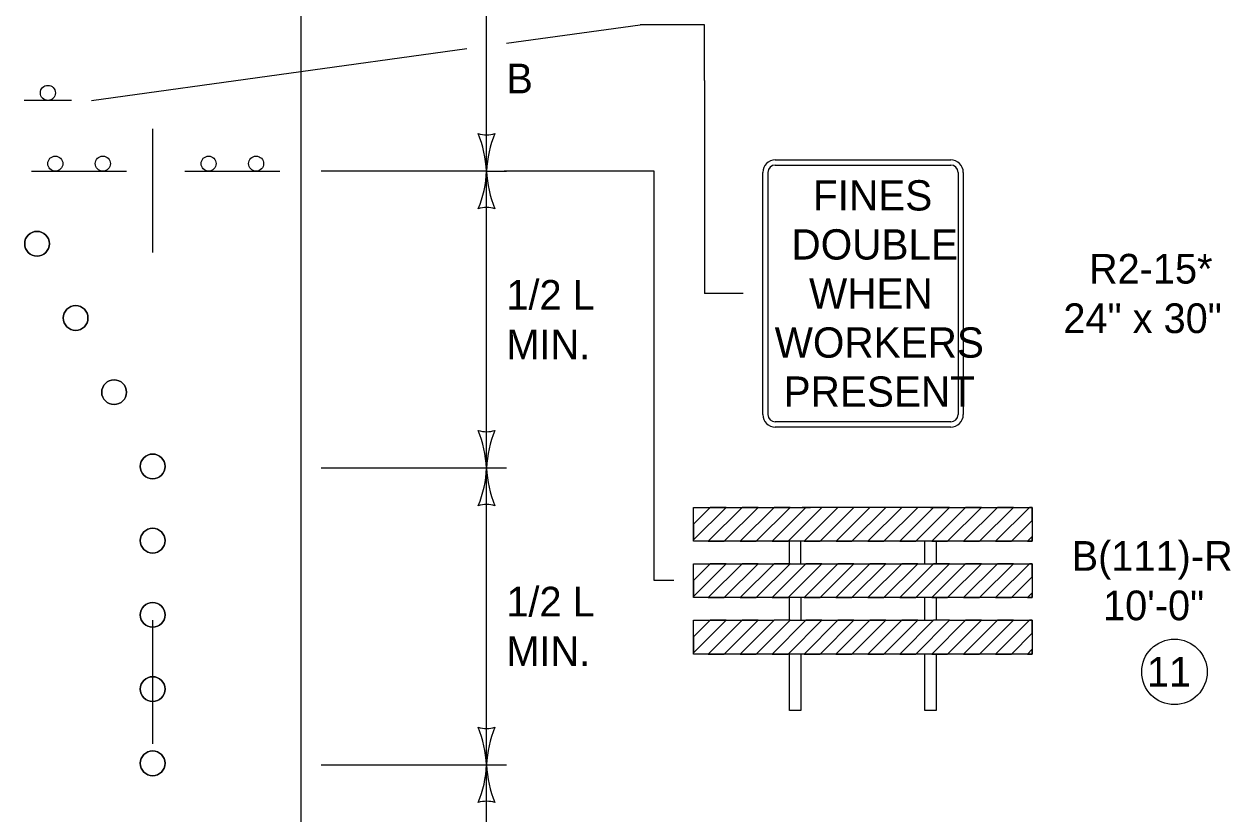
# Model space of a CAD drawing. Extents: x 49991.4 to 50021, y 49987.6 to 50011.4.
# Drawn here: x 50001.907 to 50004.345, y 49990.799 to 49992.395 of the extents above; entities that cross this region are included whole.
import ezdxf

# ---------------------------------------------------------------- set-up
doc = ezdxf.new("R2010")
doc.units = 0
for name, color, linetype in [('Level 1', 7, 'Continuous'), ('Level 2', 7, 'Continuous'), ('Level 3', 7, 'Continuous')]:
    doc.layers.add(name, color=color, linetype=linetype)

# ---------------------------------------------------------------- blocks, each defined once
blk = doc.blocks.new('ARR')
at = {"layer": 'Level 3'}
for centre, radius, start, end in [((1.53, 37.02), 37.05, 247.456, 267.6395), ((-21.37, 0), 9.13, 342.1388, 17.8612), ((1.92, -38.79), 38.83, 92.8273, 112.0772)]:
    blk.add_arc(centre, radius, start, end, dxfattribs=at)

msp = doc.modelspace()

# ---------------------------------------------------------------- linework, layer by layer
at = {"layer": 'Level 1'}
for p, q in [((50002.4673, 49988.1586), (50002.4673, 49992.9404)), ((50002.0033, 49992.2408), (50001.9073, 49992.2408)), ((50002.167, 49991.9331), (50002.167, 49992.1831)), ((50003.425, 49992.1205), (50003.7795, 49992.1205)), ((50003.425, 49992.11), (50003.7795, 49992.11)), ((50003.6023, 49992.1205), (50003.6023, 49992.1205)), ((50001.9223, 49992.0977), (50002.0183, 49992.0977)), ((50002.0183, 49992.0977), (50002.1143, 49992.0977)), ((50002.232, 49992.0977), (50002.328, 49992.0977)), ((50002.328, 49992.0977), (50002.424, 49992.0977)), ((50003.3997, 49991.6058), (50003.3997, 49992.0952)), ((50003.4103, 49991.6058), (50003.4103, 49992.0952)), ((50003.7942, 49992.0952), (50003.7942, 49991.6058)), ((50003.8048, 49992.0952), (50003.8048, 49991.6058)), ((50001.9084, 49991.951), (50001.9084, 49991.951)), ((50001.9863, 49991.801), (50001.9863, 49991.801)), ((50002.0641, 49991.651), (50002.0641, 49991.651)), ((50003.7795, 49991.591), (50003.425, 49991.591)), ((50003.7795, 49991.5805), (50003.425, 49991.5805)), ((50002.142, 49991.501), (50002.142, 49991.501)), ((50003.2599, 49991.3524), (50003.3258, 49991.4182)), ((50003.2599, 49991.3846), (50003.2935, 49991.4182)), ((50003.2935, 49991.4182), (50003.2599, 49991.3846)), ((50003.2599, 49991.3524), (50003.3258, 49991.4182)), ((50003.2896, 49991.3498), (50003.358, 49991.4182)), ((50003.358, 49991.4182), (50003.2896, 49991.3498)), ((50003.3218, 49991.3498), (50003.3902, 49991.4182)), ((50003.3218, 49991.3498), (50003.3902, 49991.4182)), ((50003.3541, 49991.3498), (50003.4225, 49991.4182)), ((50003.4225, 49991.4182), (50003.3541, 49991.3498)), ((50003.3863, 49991.3498), (50003.4547, 49991.4182)), ((50003.3863, 49991.3498), (50003.4547, 49991.4182)), ((50003.4186, 49991.3498), (50003.4869, 49991.4182)), ((50003.4508, 49991.3498), (50003.5192, 49991.4182)), ((50003.4651, 49991.4182), (50003.4964, 49991.4182)), ((50003.7244, 49991.4182), (50003.4794, 49991.4182)), ((50003.4832, 49991.3498), (50003.5516, 49991.4182)), ((50003.5154, 49991.3498), (50003.5838, 49991.4182)), ((50003.5476, 49991.3498), (50003.616, 49991.4182)), ((50003.5798, 49991.3498), (50003.6482, 49991.4182)), ((50003.612, 49991.3498), (50003.6804, 49991.4182)), ((50003.6443, 49991.3498), (50003.7126, 49991.4182)), ((50003.6765, 49991.3498), (50003.7448, 49991.4182)), ((50003.7448, 49991.4182), (50003.7049, 49991.4182)), ((50003.7087, 49991.3498), (50003.7771, 49991.4182)), ((50003.7409, 49991.3498), (50003.8093, 49991.4182)), ((50003.8093, 49991.4182), (50003.7409, 49991.3498)), ((50003.7732, 49991.3498), (50003.8416, 49991.4182)), ((50003.7732, 49991.3498), (50003.8416, 49991.4182)), ((50003.8054, 49991.3498), (50003.8738, 49991.4182)), ((50003.8738, 49991.4182), (50003.8054, 49991.3498)), ((50003.8376, 49991.3498), (50003.906, 49991.4182)), ((50003.8376, 49991.3498), (50003.906, 49991.4182)), ((50003.8699, 49991.3498), (50003.9383, 49991.4182)), ((50003.9383, 49991.4182), (50003.8699, 49991.3498)), ((50003.9021, 49991.3498), (50003.9439, 49991.3916)), ((50003.9021, 49991.3498), (50003.9439, 49991.3916)), ((50002.142, 49991.351), (50002.142, 49991.351)), ((50003.4765, 49991.3043), (50003.4765, 49991.3498)), ((50003.7273, 49991.3043), (50003.7273, 49991.3498)), ((50003.9344, 49991.3498), (50003.9439, 49991.3593)), ((50003.9439, 49991.3593), (50003.9344, 49991.3498)), ((50003.2599, 49991.2384), (50003.3258, 49991.3043)), ((50003.2599, 49991.2706), (50003.2935, 49991.3043)), ((50003.2935, 49991.3043), (50003.2599, 49991.2706)), ((50003.2599, 49991.2384), (50003.3258, 49991.3043)), ((50003.2896, 49991.2359), (50003.358, 49991.3043)), ((50003.358, 49991.3043), (50003.2896, 49991.2359)), ((50003.3218, 49991.2359), (50003.3902, 49991.3043)), ((50003.3218, 49991.2359), (50003.3902, 49991.3043)), ((50003.3541, 49991.2359), (50003.4225, 49991.3043)), ((50003.4225, 49991.3043), (50003.3541, 49991.2359)), ((50003.3863, 49991.2359), (50003.4547, 49991.3043)), ((50003.3863, 49991.2359), (50003.4547, 49991.3043)), ((50003.4186, 49991.2359), (50003.4869, 49991.3043)), ((50003.4508, 49991.2359), (50003.5192, 49991.3043)), ((50003.483, 49991.2359), (50003.5514, 49991.3043)), ((50003.5153, 49991.2359), (50003.5837, 49991.3043)), ((50003.5475, 49991.2359), (50003.6159, 49991.3043)), ((50003.5797, 49991.2359), (50003.6481, 49991.3043)), ((50003.612, 49991.2359), (50003.6804, 49991.3043)), ((50003.6442, 49991.2359), (50003.7126, 49991.3043)), ((50003.6765, 49991.2359), (50003.7387, 49991.2981)), ((50003.7387, 49991.2659), (50003.7771, 49991.3043)), ((50003.7387, 49991.2981), (50003.7448, 49991.3043)), ((50003.7409, 49991.2359), (50003.8093, 49991.3043)), ((50003.8093, 49991.3043), (50003.7409, 49991.2359)), ((50003.7732, 49991.2359), (50003.8416, 49991.3043)), ((50003.7732, 49991.2359), (50003.8416, 49991.3043)), ((50003.8054, 49991.2359), (50003.8738, 49991.3043)), ((50003.8738, 49991.3043), (50003.8054, 49991.2359)), ((50003.8376, 49991.2359), (50003.906, 49991.3043)), ((50003.8376, 49991.2359), (50003.906, 49991.3043)), ((50003.8699, 49991.2359), (50003.9383, 49991.3043)), ((50003.9383, 49991.3043), (50003.8699, 49991.2359)), ((50003.9021, 49991.2359), (50003.9439, 49991.2776)), ((50003.9021, 49991.2359), (50003.9439, 49991.2776)), ((50003.7087, 49991.2359), (50003.7387, 49991.2659)), ((50003.9344, 49991.2359), (50003.9439, 49991.2454)), ((50003.9439, 49991.2454), (50003.9344, 49991.2359)), ((50002.142, 49991.201), (50002.142, 49991.201)), ((50002.1674, 49990.9404), (50002.1674, 49991.1904)), ((50003.2599, 49991.1244), (50003.3258, 49991.1903)), ((50003.2599, 49991.1567), (50003.2935, 49991.1903)), ((50003.2935, 49991.1903), (50003.2599, 49991.1567)), ((50003.2599, 49991.1244), (50003.3258, 49991.1903)), ((50003.2896, 49991.1219), (50003.358, 49991.1903)), ((50003.358, 49991.1903), (50003.2896, 49991.1219)), ((50003.3218, 49991.1219), (50003.3902, 49991.1903)), ((50003.3218, 49991.1219), (50003.3902, 49991.1903)), ((50003.3541, 49991.1219), (50003.4225, 49991.1903)), ((50003.4225, 49991.1903), (50003.3541, 49991.1219)), ((50003.3863, 49991.1219), (50003.4547, 49991.1903)), ((50003.3863, 49991.1219), (50003.4547, 49991.1903)), ((50003.4186, 49991.1219), (50003.4869, 49991.1903)), ((50003.4869, 49991.1903), (50003.4186, 49991.1219)), ((50003.4508, 49991.1219), (50003.5192, 49991.1903)), ((50003.4508, 49991.1219), (50003.5192, 49991.1903)), ((50003.483, 49991.1219), (50003.5514, 49991.1903)), ((50003.5514, 49991.1903), (50003.483, 49991.1219)), ((50003.5153, 49991.1219), (50003.5837, 49991.1903)), ((50003.5153, 49991.1219), (50003.5837, 49991.1903)), ((50003.5475, 49991.1219), (50003.6159, 49991.1903)), ((50003.6159, 49991.1903), (50003.5475, 49991.1219)), ((50003.5797, 49991.1219), (50003.6481, 49991.1903)), ((50003.5797, 49991.1219), (50003.6481, 49991.1903)), ((50003.612, 49991.1219), (50003.6804, 49991.1903)), ((50003.6804, 49991.1903), (50003.612, 49991.1219)), ((50003.6442, 49991.1219), (50003.7126, 49991.1903)), ((50003.6442, 49991.1219), (50003.7126, 49991.1903)), ((50003.6765, 49991.1219), (50003.7448, 49991.1903)), ((50003.7448, 49991.1903), (50003.6765, 49991.1219)), ((50003.7087, 49991.1219), (50003.7771, 49991.1903)), ((50003.7087, 49991.1219), (50003.7771, 49991.1903)), ((50003.7409, 49991.1219), (50003.8093, 49991.1903)), ((50003.8093, 49991.1903), (50003.7409, 49991.1219)), ((50003.7732, 49991.1219), (50003.8416, 49991.1903)), ((50003.7732, 49991.1219), (50003.8416, 49991.1903)), ((50003.8054, 49991.1219), (50003.8738, 49991.1903)), ((50003.8738, 49991.1903), (50003.8054, 49991.1219)), ((50003.8376, 49991.1219), (50003.906, 49991.1903)), ((50003.8376, 49991.1219), (50003.906, 49991.1903)), ((50003.8699, 49991.1219), (50003.9383, 49991.1903)), ((50003.9383, 49991.1903), (50003.8699, 49991.1219)), ((50003.9021, 49991.1219), (50003.9439, 49991.1637)), ((50003.9021, 49991.1219), (50003.9439, 49991.1637)), ((50003.9344, 49991.1219), (50003.9439, 49991.1315)), ((50003.9439, 49991.1315), (50003.9344, 49991.1219)), ((50002.142, 49991.051), (50002.142, 49991.051)), ((50002.142, 49990.901), (50002.142, 49990.901))]:
    msp.add_line(p, q, dxfattribs=at)
for points in [[(50003.7387, 49991.3498), (50003.2599, 49991.3498), (50003.2599, 49991.4182), (50003.4651, 49991.4182)], [(50003.3258, 49991.4182), (50003.2935, 49991.4182)], [(50003.3902, 49991.4182), (50003.358, 49991.4182)], [(50003.5192, 49991.4182), (50003.4964, 49991.4182), (50003.4869, 49991.4182), (50003.4186, 49991.3498), (50003.4508, 49991.3498), (50003.5192, 49991.4182)], [(50003.4547, 49991.4182), (50003.4225, 49991.4182)], [(50003.5838, 49991.4182), (50003.5516, 49991.4182), (50003.4832, 49991.3498), (50003.5154, 49991.3498), (50003.5838, 49991.4182)], [(50003.6482, 49991.4182), (50003.616, 49991.4182), (50003.5476, 49991.3498), (50003.5798, 49991.3498), (50003.6482, 49991.4182)], [(50003.7126, 49991.4182), (50003.7049, 49991.4182), (50003.6804, 49991.4182), (50003.612, 49991.3498), (50003.6443, 49991.3498), (50003.7126, 49991.4182)], [(50003.6765, 49991.3498), (50003.7087, 49991.3498), (50003.7771, 49991.4182), (50003.7448, 49991.4182), (50003.6765, 49991.3498)], [(50003.7387, 49991.4182), (50003.9439, 49991.4182), (50003.9439, 49991.3498), (50003.7387, 49991.3498)], [(50003.8416, 49991.4182), (50003.8093, 49991.4182)], [(50003.906, 49991.4182), (50003.8738, 49991.4182)], [(50003.9439, 49991.3916), (50003.9439, 49991.4182), (50003.9383, 49991.4182)], [(50003.2599, 49991.3846), (50003.2599, 49991.3524)], [(50003.2896, 49991.3498), (50003.3218, 49991.3498)], [(50003.3541, 49991.3498), (50003.3863, 49991.3498)], [(50003.4537, 49991.3042), (50003.4537, 49991.3498)], [(50003.7409, 49991.3498), (50003.7732, 49991.3498)], [(50003.7501, 49991.3498), (50003.7501, 49991.3043)], [(50003.8054, 49991.3498), (50003.8376, 49991.3498)], [(50003.8699, 49991.3498), (50003.9021, 49991.3498)], [(50003.9344, 49991.3498), (50003.9439, 49991.3498), (50003.9439, 49991.3593)], [(50003.7387, 49991.3043), (50003.9439, 49991.3043), (50003.9439, 49991.2359), (50003.2599, 49991.2359), (50003.2599, 49991.3043), (50003.7387, 49991.3043)], [(50003.3258, 49991.3043), (50003.2935, 49991.3043)], [(50003.3902, 49991.3043), (50003.358, 49991.3043)], [(50003.5192, 49991.3043), (50003.4869, 49991.3043), (50003.4186, 49991.2359), (50003.4508, 49991.2359), (50003.5192, 49991.3043)], [(50003.4547, 49991.3043), (50003.4225, 49991.3043)], [(50003.5837, 49991.3043), (50003.5514, 49991.3043), (50003.483, 49991.2359), (50003.5153, 49991.2359), (50003.5837, 49991.3043)], [(50003.6481, 49991.3043), (50003.6159, 49991.3043), (50003.5475, 49991.2359), (50003.5797, 49991.2359), (50003.6481, 49991.3043)], [(50003.7126, 49991.3043), (50003.6804, 49991.3043), (50003.612, 49991.2359), (50003.6442, 49991.2359), (50003.7126, 49991.3043)], [(50003.6765, 49991.2359), (50003.7087, 49991.2359), (50003.7387, 49991.2659), (50003.7771, 49991.3043), (50003.7501, 49991.3043), (50003.7448, 49991.3043), (50003.7387, 49991.2981), (50003.6765, 49991.2359)], [(50003.8416, 49991.3043), (50003.8093, 49991.3043)], [(50003.906, 49991.3043), (50003.8738, 49991.3043)], [(50003.9439, 49991.2776), (50003.9439, 49991.3043), (50003.9383, 49991.3043)], [(50003.2599, 49991.2706), (50003.2599, 49991.2384)], [(50003.2896, 49991.2359), (50003.3218, 49991.2359)], [(50003.3541, 49991.2359), (50003.3863, 49991.2359)], [(50003.4537, 49991.1903), (50003.4537, 49991.2359)], [(50003.4765, 49991.2359), (50003.4765, 49991.1903)], [(50003.7273, 49991.1903), (50003.7273, 49991.2359)], [(50003.7409, 49991.2359), (50003.7732, 49991.2359)], [(50003.7501, 49991.2359), (50003.7501, 49991.1903)], [(50003.8054, 49991.2359), (50003.8376, 49991.2359)], [(50003.8699, 49991.2359), (50003.9021, 49991.2359)], [(50003.9344, 49991.2359), (50003.9439, 49991.2359), (50003.9439, 49991.2454)], [(50003.7771, 49991.1903), (50003.9439, 49991.1903), (50003.9439, 49991.1219), (50003.2599, 49991.1219), (50003.2599, 49991.1903), (50003.4225, 49991.1903)], [(50003.3258, 49991.1903), (50003.2935, 49991.1903)], [(50003.3902, 49991.1903), (50003.358, 49991.1903)], [(50003.4547, 49991.1903), (50003.4225, 49991.1903)], [(50003.4547, 49991.1903), (50003.7448, 49991.1903)], [(50003.5192, 49991.1903), (50003.4869, 49991.1903)], [(50003.5837, 49991.1903), (50003.5514, 49991.1903)], [(50003.6481, 49991.1903), (50003.6159, 49991.1903)], [(50003.7126, 49991.1903), (50003.6804, 49991.1903)], [(50003.7771, 49991.1903), (50003.7448, 49991.1903)], [(50003.8416, 49991.1903), (50003.8093, 49991.1903)], [(50003.906, 49991.1903), (50003.8738, 49991.1903)], [(50003.9439, 49991.1637), (50003.9439, 49991.1903), (50003.9383, 49991.1903)], [(50003.2599, 49991.1567), (50003.2599, 49991.1244)], [(50003.9344, 49991.1219), (50003.9439, 49991.1219), (50003.9439, 49991.1315)], [(50003.2896, 49991.1219), (50003.3218, 49991.1219)], [(50003.3541, 49991.1219), (50003.3863, 49991.1219)], [(50003.4186, 49991.1219), (50003.4508, 49991.1219)], [(50003.4765, 49991.1218), (50003.4765, 49991.0078), (50003.4537, 49991.0078), (50003.4537, 49991.1218)], [(50003.483, 49991.1219), (50003.5153, 49991.1219)], [(50003.5475, 49991.1219), (50003.5797, 49991.1219)], [(50003.612, 49991.1219), (50003.6442, 49991.1219)], [(50003.6765, 49991.1219), (50003.7087, 49991.1219)], [(50003.7501, 49991.1218), (50003.7501, 49991.0078), (50003.7273, 49991.0078), (50003.7273, 49991.1218)], [(50003.7409, 49991.1219), (50003.7732, 49991.1219)], [(50003.8054, 49991.1219), (50003.8376, 49991.1219)], [(50003.8699, 49991.1219), (50003.9021, 49991.1219)]]:
    msp.add_lwpolyline(points, dxfattribs=at)
for centre, radius in [((50001.9553, 49992.2559), 0.0152), ((50001.9703, 49992.1129), 0.0152), ((50002.0663, 49992.1129), 0.0152), ((50002.28, 49992.1129), 0.0152), ((50002.376, 49992.1129), 0.0152), ((50001.9334, 49991.951), 0.025), ((50002.0113, 49991.801), 0.025), ((50002.0891, 49991.651), 0.025), ((50002.167, 49991.501), 0.025), ((50002.167, 49991.351), 0.025), ((50002.167, 49991.201), 0.025), ((50002.167, 49991.051), 0.025), ((50002.167, 49990.901), 0.025)]:
    msp.add_circle(centre, radius, dxfattribs=at)
for centre, radius, start, end in [((50003.425, 49992.0952), 0.0253, 90, 180), ((50003.425, 49992.0952), 0.0148, 90, 180), ((50003.7795, 49992.0952), 0.0253, 0, 90), ((50003.7795, 49992.0952), 0.0148, 0, 90), ((50001.9334, 49991.951), 0.025, 0, 180), ((50001.9334, 49991.951), 0.025, 180, 0), ((50002.0113, 49991.801), 0.025, 0, 180), ((50002.0113, 49991.801), 0.025, 180, 0), ((50002.0891, 49991.651), 0.025, 0, 180), ((50002.0891, 49991.651), 0.025, 180, 0), ((50003.425, 49991.6058), 0.0253, 180, 270), ((50003.425, 49991.6058), 0.0148, 180, 270), ((50003.7795, 49991.6058), 0.0148, 270, 360), ((50003.7795, 49991.6058), 0.0253, 270, 360), ((50002.167, 49991.501), 0.025, 0, 180), ((50002.167, 49991.501), 0.025, 180, 0), ((50002.167, 49991.351), 0.025, 0, 180), ((50002.167, 49991.351), 0.025, 180, 0), ((50002.167, 49991.201), 0.025, 0, 180), ((50002.167, 49991.201), 0.025, 180, 0), ((50002.167, 49991.051), 0.025, 0, 180), ((50002.167, 49991.051), 0.025, 180, 0), ((50002.167, 49990.901), 0.025, 0, 180), ((50002.167, 49990.901), 0.025, 180, 0)]:
    msp.add_arc(centre, radius, start, end, dxfattribs=at)
at = {"layer": 'Level 2'}
msp.add_circle((50004.2314, 49991.0858), 0.0662, dxfattribs=at)
at = {"layer": 'Level 3'}
for p, q in [((50002.8416, 49992.0977), (50002.8416, 49992.4721)), ((50002.8816, 49992.3564), (50003.1517, 49992.3937)), ((50003.2821, 49992.3937), (50003.1517, 49992.3937)), ((50003.2821, 49992.2807), (50003.2821, 49992.3937)), ((50002.0433, 49992.2408), (50002.8016, 49992.3454)), ((50002.8416, 49992.0977), (50002.5073, 49992.0977)), ((50002.8416, 49991.4977), (50002.8416, 49992.0977)), ((50002.8416, 49992.0977), (50002.8816, 49992.0977)), ((50003.3597, 49991.8505), (50003.2821, 49991.8505)), ((50002.8816, 49991.4977), (50002.5073, 49991.4977)), ((50002.8416, 49990.8977), (50002.8416, 49991.4977)), ((50002.5073, 49990.8977), (50002.8816, 49990.8977)), ((50002.8416, 49990.2977), (50002.8416, 49990.8977))]:
    msp.add_line(p, q, dxfattribs=at)
for points in [[(50003.2821, 49992.2807), (50003.2821, 49991.8505)], [(50003.2199, 49991.2706), (50003.1799, 49991.2706), (50003.1799, 49992.0977), (50002.8771, 49992.0977)]]:
    msp.add_lwpolyline(points, dxfattribs=at)
for centre, radius, start, end in [((50002.6194, 49990.9069), 0.2223, 337.456, 357.6395), ((50003.0743, 49990.9092), 0.233, 182.8273, 202.0772), ((50002.8416, 49990.7695), 0.0548, 72.1388, 107.8612)]:
    msp.add_arc(centre, radius, start, end, dxfattribs=at)

# ---------------------------------------------------------------- block references
at = {"layer": 'Level 3', "xscale": 0.006, "yscale": 0.006}
for p, rotation in [((50002.8416, 49992.0977), -90), ((50002.8416, 49992.0977), 90), ((50002.8416, 49991.4977), -90), ((50002.8416, 49991.4977), 90), ((50002.8416, 49990.8977), -90)]:
    msp.add_blockref('ARR', p, dxfattribs=dict(at, rotation=rotation))

# ---------------------------------------------------------------- texts
at = {"layer": 'Level 1'}
for s, p in [('FINES', (50003.5011, 49992.0182)), ('DOUBLE', (50003.4576, 49991.9191)), ('WHEN', (50003.4931, 49991.8199)), ('WORKERS', (50003.4237, 49991.7208)), ('PRESENT', (50003.4418, 49991.6216))]:
    msp.add_text(s, height=0.06118, dxfattribs=at).set_placement(p)
at = {"layer": 'Level 2'}
for s, height, p in [('B', 0.06, (50002.8816, 49992.2549)), ('R2-15*', 0.06, (50004.0586, 49991.8705)), ('1/2 L', 0.06, (50002.8816, 49991.8177)), ('24" x 30"', 0.06, (50004.007, 49991.7705)), ('MIN.', 0.06, (50002.8816, 49991.7177)), ('B(111)-R', 0.06, (50004.0236, 49991.2901)), ('1/2 L', 0.06, (50002.8816, 49991.1977)), ('10\'-0"', 0.06, (50004.0871, 49991.1901)), ('MIN.', 0.06, (50002.8816, 49991.0977)), ('11', 0.06006, (50004.1757, 49991.0559))]:
    msp.add_text(s, height=height, dxfattribs=at).set_placement(p)

doc.saveas('drawing.dxf')
